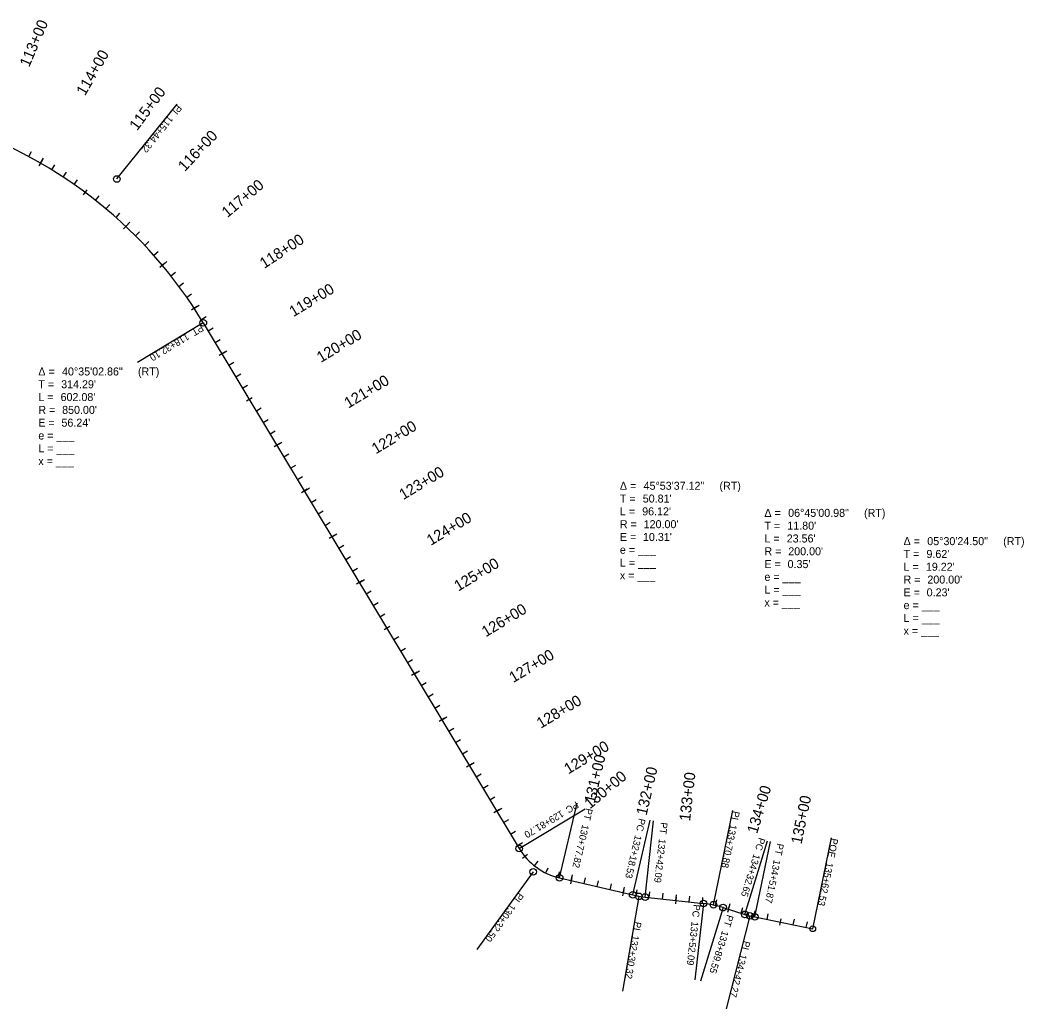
# Model space of a CAD drawing. Extents: x 14106984 to 14110066, y 8637277 to 8639226.
# Drawn here: x 14108185 to 14110066, y 8637277 to 8639130 of the extents above; entities that cross this region are included whole.
import ezdxf

# ---------------------------------------------------------------- set-up
doc = ezdxf.new("R2010")
doc.units = 0
for name, color, linetype in [('Alignment', 7, 'Continuous'), ('Default', 7, 'Continuous'), ('TextAlignment', 7, 'Continuous'), ('TextAlignmentLrg', 7, 'Continuous'), ('TextAlignmentSml', 7, 'Continuous')]:
    doc.layers.add(name, color=color, linetype=linetype)

msp = doc.modelspace()

# ---------------------------------------------------------------- linework, layer by layer
at = {"layer": 'Alignment'}
for p, q in [((14108528.3, 8638562.6), (14109120.4, 8637577.2)), ((14109196.1, 8637522.2), (14109333.1, 8637490.3)), ((14109356.4, 8637486.3), (14109465.7, 8637474.1)), ((14109502.3, 8637466.5), (14109543.5, 8637453.8)), ((14109562.1, 8637449.1), (14109670.5, 8637426.9))]:
    msp.add_line(p, q, dxfattribs=at)
for centre, radius, start, end in [((14107799.7, 8638124.7), 850, 31.0039, 71.588), ((14109223.3, 8637639), 120, 211.0039, 256.8975), ((14109378.5, 8637685), 200, 256.8975, 263.6478), ((14109443.6, 8637275.3), 200, 72.9168, 83.6478), ((14109602.3, 8637645), 200, 252.9168, 258.4236)]:
    msp.add_arc(centre, radius, start, end, dxfattribs=at)
at = {"layer": 'Default'}
for p, q in [((14108528.3, 8638562.6), (14109120.4, 8637577.2)), ((14109196.1, 8637522.2), (14109333.1, 8637490.3)), ((14109356.4, 8637486.3), (14109465.7, 8637474.1)), ((14109502.3, 8637466.5), (14109543.5, 8637453.8)), ((14109562.1, 8637449.1), (14109670.5, 8637426.9))]:
    msp.add_line(p, q, dxfattribs=at)
for centre, radius, start, end in [((14107799.7, 8638124.7), 850, 31.0039, 71.588), ((14109223.3, 8637639), 120, 211.0039, 256.8975), ((14109378.5, 8637685), 200, 256.8975, 263.6478), ((14109443.6, 8637275.3), 200, 72.9168, 83.6478), ((14109602.3, 8637645), 200, 252.9168, 258.4236)]:
    msp.add_arc(centre, radius, start, end, dxfattribs=at)
at = {"layer": 'TextAlignment'}
for p, q in [((14108366.4, 8638832), (14108479, 8638972.4)), ((14108528.3, 8638562.6), (14108404.9, 8638488.4)), ((14109196.1, 8637522.2), (14109228.7, 8637662.4)), ((14109120.4, 8637577.2), (14109243.9, 8637651.4)), ((14109484.4, 8637472), (14109520.9, 8637648.3)), ((14109333.1, 8637490.3), (14109365.8, 8637630.5)), ((14109356.4, 8637486.3), (14109372.3, 8637629.4)), ((14109670.5, 8637426.9), (14109705.4, 8637597.3)), ((14109543.5, 8637453.8), (14109585.8, 8637591.5)), ((14109562.1, 8637449.1), (14109591, 8637590.2)), ((14109146.6, 8637533.7), (14109040.7, 8637388.1)), ((14109344.6, 8637487.6), (14109314.2, 8637310.2)), ((14109465.7, 8637474.1), (14109449.7, 8637331)), ((14109502.3, 8637466.5), (14109460, 8637328.9)), ((14109552.7, 8637451), (14109508.1, 8637276.6))]:
    msp.add_line(p, q, dxfattribs=at)
for centre, radius in [((14108366.4, 8638832), 6.24), ((14108333.4, 8638786.3), 0.05), ((14108528.3, 8638562.6), 6.24), ((14109120.4, 8637577.2), 6.24), ((14109142.3, 8637550.5), 0.05), ((14109146.6, 8637533.7), 6.24), ((14109196.1, 8637522.2), 6.24), ((14109333.1, 8637490.3), 6.24), ((14109344.6, 8637487.6), 6.24), ((14109343, 8637488.2), 0.05), ((14109356.4, 8637486.3), 6.24), ((14109465.7, 8637474.1), 6.24), ((14109484.4, 8637472), 6.24), ((14109502.3, 8637466.5), 6.24), ((14109543.5, 8637453.8), 6.24), ((14109552.7, 8637451), 6.24), ((14109562.1, 8637449.1), 6.24), ((14109556.7, 8637450.3), 0.05), ((14109670.5, 8637426.9), 5.34)]:
    msp.add_circle(centre, radius, dxfattribs=at)
at = {"layer": 'TextAlignmentLrg'}
for p, q in [((14108223, 8638861.8), (14108228.5, 8638871.3)), ((14108310.3, 8638812), (14108303, 8638802.1)), ((14108383.2, 8638742.8), (14108390.7, 8638750.8)), ((14108451.7, 8638670.1), (14108460.1, 8638677.1)), ((14108511.2, 8638589.8), (14108520.4, 8638595.7)), ((14108563.3, 8638504.4), (14108572.6, 8638510)), ((14108620, 8638421.8), (14108609.5, 8638415.5)), ((14108666.3, 8638332.9), (14108675.6, 8638338.6)), ((14108717.8, 8638247.2), (14108727.2, 8638252.9)), ((14108769.3, 8638161.5), (14108778.7, 8638167.1)), ((14108820.8, 8638075.8), (14108830.2, 8638081.4)), ((14108877.6, 8637993.2), (14108867.1, 8637986.9)), ((14108923.8, 8637904.4), (14108933.2, 8637910)), ((14108975.3, 8637818.7), (14108984.7, 8637824.3)), ((14109026.8, 8637733), (14109036.2, 8637738.6)), ((14109078.4, 8637647.2), (14109087.7, 8637652.9)), ((14109135.7, 8637566.2), (14109126.3, 8637558.4)), ((14109217.7, 8637517.1), (14109220.2, 8637527.8)), ((14109315.1, 8637494.5), (14109317.6, 8637505.1)), ((14109413.9, 8637479.9), (14109415.1, 8637490.7)), ((14109512.3, 8637463.4), (14109515.5, 8637473.9)), ((14109610.5, 8637445.4), (14109608, 8637433.4))]:
    msp.add_line(p, q, dxfattribs=at)
for centre in [(14109139, 8637546.7), (14109344.7, 8637487.9), (14109552.8, 8637451.2)]:
    msp.add_circle(centre, 0.05, dxfattribs=at)
at = {"layer": 'TextAlignmentSml'}
for p, q in [((14108201.2, 8638874), (14108206.3, 8638883.6)), ((14108226.1, 8638867.1), (14108220, 8638856.5)), ((14108244.5, 8638849.1), (14108250.3, 8638858.4)), ((14108265.7, 8638835.7), (14108271.6, 8638844.8)), ((14108286.4, 8638821.7), (14108292.6, 8638830.6)), ((14108310.3, 8638812), (14108303, 8638802.1)), ((14108326.5, 8638791.8), (14108333.3, 8638800.4)), ((14108345.9, 8638776.1), (14108352.9, 8638784.4)), ((14108364.8, 8638759.7), (14108372.1, 8638767.9)), ((14108387.4, 8638747.3), (14108379, 8638738.4)), ((14108401.1, 8638725.4), (14108408.9, 8638733.1)), ((14108418.5, 8638707.5), (14108426.5, 8638714.9)), ((14108435.4, 8638689), (14108443.6, 8638696.3)), ((14108456.4, 8638674), (14108447, 8638666.1)), ((14108467.5, 8638650.7), (14108476.1, 8638657.4)), ((14108482.7, 8638630.8), (14108491.4, 8638637.3)), ((14108497.3, 8638610.5), (14108506.2, 8638616.7)), ((14108516.4, 8638593.1), (14108506.1, 8638586.4)), ((14108524.6, 8638568.6), (14108533.9, 8638574.3)), ((14108537.5, 8638547.2), (14108546.9, 8638552.9)), ((14108550.4, 8638525.8), (14108559.7, 8638531.4)), ((14108568.5, 8638507.5), (14108558, 8638501.2)), ((14108576.1, 8638482.9), (14108585.5, 8638488.6)), ((14108589, 8638461.5), (14108598.4, 8638467.1)), ((14108601.9, 8638440.1), (14108611.3, 8638445.7)), ((14108620, 8638421.8), (14108609.5, 8638415.5)), ((14108627.7, 8638397.2), (14108637, 8638402.9)), ((14108640.5, 8638375.8), (14108649.9, 8638381.4)), ((14108653.4, 8638354.4), (14108662.8, 8638360)), ((14108671.5, 8638336.1), (14108661, 8638329.8)), ((14108679.2, 8638311.5), (14108688.5, 8638317.1)), ((14108692, 8638290.1), (14108701.4, 8638295.7)), ((14108704.9, 8638268.7), (14108714.3, 8638274.3)), ((14108723, 8638250.4), (14108712.5, 8638244.1)), ((14108730.7, 8638225.8), (14108740, 8638231.4)), ((14108743.5, 8638204.4), (14108752.9, 8638210)), ((14108756.4, 8638182.9), (14108765.8, 8638188.6)), ((14108774.5, 8638164.7), (14108764.1, 8638158.4)), ((14108782.2, 8638140.1), (14108791.5, 8638145.7)), ((14108795.1, 8638118.7), (14108804.4, 8638124.3)), ((14108807.9, 8638097.2), (14108817.3, 8638102.9)), ((14108826.1, 8638079), (14108815.6, 8638072.7)), ((14108833.7, 8638054.4), (14108843, 8638060)), ((14108846.6, 8638032.9), (14108855.9, 8638038.6)), ((14108859.4, 8638011.5), (14108868.8, 8638017.1)), ((14108877.6, 8637993.2), (14108867.1, 8637986.9)), ((14108885.2, 8637968.7), (14108894.6, 8637974.3)), ((14108898.1, 8637947.2), (14108907.4, 8637952.9)), ((14108911, 8637925.8), (14108920.3, 8637931.4)), ((14108929.1, 8637907.5), (14108918.6, 8637901.2)), ((14108936.7, 8637883), (14108946.1, 8637888.6)), ((14108949.6, 8637861.5), (14108958.9, 8637867.1)), ((14108962.5, 8637840.1), (14108971.8, 8637845.7)), ((14108980.6, 8637821.8), (14108970.1, 8637815.5)), ((14108988.2, 8637797.2), (14108997.6, 8637802.9)), ((14109001.1, 8637775.8), (14109010.5, 8637781.4)), ((14109014, 8637754.4), (14109023.3, 8637760)), ((14109032.1, 8637736.1), (14109021.6, 8637729.8)), ((14109039.7, 8637711.5), (14109049.1, 8637717.1)), ((14109052.6, 8637690.1), (14109062, 8637695.7)), ((14109065.5, 8637668.7), (14109074.8, 8637674.3)), ((14109083.6, 8637650.4), (14109073.1, 8637644.1)), ((14109091.2, 8637625.8), (14109100.6, 8637631.4)), ((14109104.1, 8637604.4), (14109113.5, 8637610)), ((14109117, 8637583), (14109126.4, 8637588.6)), ((14109135.7, 8637566.2), (14109126.3, 8637558.4)), ((14109148.9, 8637544.9), (14109155.7, 8637553.4)), ((14109170, 8637531.5), (14109174.8, 8637541.3)), ((14109193.4, 8637522.8), (14109196.1, 8637533.4)), ((14109219.1, 8637523.1), (14109216.3, 8637511.2)), ((14109242, 8637511.5), (14109244.5, 8637522.1)), ((14109266.4, 8637505.8), (14109268.9, 8637516.4)), ((14109290.7, 8637500.1), (14109293.2, 8637510.8)), ((14109316.5, 8637500.4), (14109313.7, 8637488.5)), ((14109339.5, 8637488.9), (14109341.6, 8637499.6)), ((14109364.2, 8637485.4), (14109365.4, 8637496.3)), ((14109389.1, 8637482.6), (14109390.3, 8637493.5)), ((14109414.6, 8637485.9), (14109413.2, 8637473.8)), ((14109438.8, 8637477.1), (14109440, 8637488)), ((14109463.6, 8637474.3), (14109464.8, 8637485.2)), ((14109488.3, 8637470.3), (14109490.7, 8637480.9)), ((14109514.1, 8637469.3), (14109510.5, 8637457.6)), ((14109536.2, 8637456.1), (14109539.4, 8637466.5)), ((14109560.3, 8637449.5), (14109562.6, 8637460.2)), ((14109584.8, 8637444.4), (14109587, 8637455.1)), ((14109610.5, 8637445.4), (14109608, 8637433.4)), ((14109633.8, 8637434.4), (14109636, 8637445.1)), ((14109658.3, 8637429.4), (14109660.4, 8637440.1))]:
    msp.add_line(p, q, dxfattribs=at)

# ---------------------------------------------------------------- texts
at = {"layer": 'TextAlignment'}
for s, rotation, p in [('PI ', 231.2959, (14108479.2, 8638972.3)), ('115+44.32', 231.2959, (14108463, 8638952.1)), ('PT', 211.0039, (14108523.9, 8638559.7)), ('118+32.10', 211.0039, (14108497.1, 8638543.5)), ('PC', 211.0039, (14109226.7, 8637666.1)), ('129+81.70', 211.0039, (14109199, 8637649.5)), ('PT', 256.8975, (14109245.8, 8637653.5)), ('PI ', 258.2823, (14109521.2, 8637648.2)), ('130+77.82', 256.8975, (14109238.7, 8637623)), ('PC', 256.8975, (14109344.8, 8637634.5)), ('PT', 263.6478, (14109385.7, 8637626.8)), ('133+70.88', 258.2823, (14109515.9, 8637622.9)), ('132+18.53', 256.8975, (14109337.5, 8637603.1)), ('PC', 252.9168, (14109569.4, 8637598.7)), ('132+42.09', 263.6478, (14109382.3, 8637595.7)), ('PT', 258.4236, (14109603.9, 8637587.7)), ('POE ', 258.4236, (14109705.7, 8637597.3)), ('134+32.65', 252.9168, (14109559.9, 8637567.9)), ('134+51.87', 258.4236, (14109597.6, 8637557)), ('135+62.53', 258.4236, (14109696.4, 8637551.8)), ('PI ', 233.9507, (14109119.3, 8637495.7)), ('130+32.50', 233.9507, (14109104.1, 8637474.8)), ('PC', 263.6478, (14109447.1, 8637473)), ('PT', 252.9168, (14109510, 8637454.1)), ('PI ', 260.2726, (14109336.9, 8637440.8)), ('133+52.09', 263.6478, (14109443.5, 8637441)), ('132+30.32', 260.2726, (14109332.5, 8637415.3)), ('133+89.55', 252.9168, (14109500.8, 8637424.2)), ('PI ', 255.6702, (14109541.2, 8637405.1)), ('134+42.27', 255.6702, (14109534.8, 8637380.1))]:
    msp.add_text(s, height=12.96, rotation=rotation, dxfattribs=at).set_placement(p)
for s, p in [('Δ = ', (14108219.1, 8638463.8)), ('40°35\'02.86"', (14108263.5, 8638463.8)), (' (RT)', (14108400.2, 8638463.8)), ('T = ', (14108219.1, 8638439.8)), ("314.29'", (14108261.9, 8638439.8)), ('L = ', (14108219.1, 8638415.8)), ("602.08'", (14108260.8, 8638415.8)), ('R = ', (14108219.1, 8638391.8)), ("850.00'", (14108263.7, 8638391.8)), ('E = ', (14108219.1, 8638367.8)), ("56.24'", (14108262.4, 8638367.8)), ('e = ___ ', (14108219.1, 8638343.8)), ('L = ___', (14108219.1, 8638319.8)), ('x = ___', (14108219.1, 8638295.8))]:
    msp.add_text(s, height=15, dxfattribs=at).set_placement(p)
at = {"layer": 'TextAlignmentLrg'}
for s, rotation, p in [('115+00', 53.3899, (14108404.3, 8638921.4)), ('120+00', 31.0039, (14108748.6, 8638487.2)), ('125+00', 31.0039, (14109006.1, 8638058.6)), ('130+00', 39.7435, (14109252.9, 8637650.4)), ('135+00', 78.4236, (14109649.4, 8637584.3))]:
    msp.add_text(s, height=20.4, rotation=rotation, dxfattribs=at).set_placement(p)
for s, p in [('Δ = ', (14109309, 8638249.6)), ('45°53\'37.12"', (14109353.4, 8638249.6)), (' (RT)', (14109490.1, 8638249.6)), ('T = ', (14109309, 8638225.6)), ("50.81'", (14109351.9, 8638225.6)), ('L = ', (14109309, 8638201.6)), ("96.12'", (14109350.8, 8638201.6)), ('Δ = ', (14109579.9, 8638198.8)), ('06°45\'00.98"', (14109624.4, 8638198.8)), (' (RT)', (14109761.1, 8638198.8)), ('R = ', (14109309, 8638177.6)), ("120.00'", (14109353.6, 8638177.6)), ('T = ', (14109579.9, 8638174.8)), ("11.80'", (14109622.8, 8638174.8)), ('E = ', (14109309, 8638153.6)), ("10.31'", (14109352.3, 8638153.6)), ('L = ', (14109579.9, 8638150.8)), ("23.56'", (14109621.7, 8638150.8)), (' (RT)', (14110021.8, 8638145.8)), ('Δ = ', (14109840.7, 8638145.8)), ('05°30\'24.50"', (14109885.1, 8638145.8)), ('e = ___ ', (14109309, 8638129.6)), ('R = ', (14109579.9, 8638126.8)), ("200.00'", (14109624.6, 8638126.8)), ('T = ', (14109840.7, 8638121.8)), ("9.62'", (14109883.6, 8638121.8)), ('L = ___', (14109309, 8638105.6)), ('E = ', (14109579.9, 8638102.8)), ("0.35'", (14109623.3, 8638102.8)), ('L = ', (14109840.7, 8638097.8)), ("19.22'", (14109882.5, 8638097.8)), ('x = ___', (14109309, 8638081.6)), ('e = ___ ', (14109579.9, 8638078.8)), ('R = ', (14109840.7, 8638073.8)), ("200.00'", (14109885.3, 8638073.8)), ('L = ___', (14109579.9, 8638054.8)), ('E = ', (14109840.7, 8638049.8)), ("0.23'", (14109884, 8638049.8)), ('x = ___', (14109579.9, 8638030.8)), ('e = ___ ', (14109840.7, 8638025.8)), ('L = ___', (14109840.7, 8638001.8)), ('x = ___', (14109840.7, 8637977.8))]:
    msp.add_text(s, height=15, dxfattribs=at).set_placement(p)
at = {"layer": 'TextAlignmentSml'}
for s, rotation, p in [('113+00', 66.8712, (14108201.9, 8639040.4)), ('114+00', 60.1305, (14108306.6, 8638986.8)), ('115+00', 53.3899, (14108404.3, 8638921.4)), ('116+00', 46.6492, (14108493.6, 8638844.9)), ('117+00', 39.9085, (14108573.3, 8638758.5)), ('118+00', 33.1678, (14108642.4, 8638663.3)), ('119+00', 31.0039, (14108697.1, 8638572.9)), ('120+00', 31.0039, (14108748.6, 8638487.2)), ('121+00', 31.0039, (14108800.1, 8638401.5)), ('122+00', 31.0039, (14108851.6, 8638315.8)), ('123+00', 31.0039, (14108903.1, 8638230)), ('124+00', 31.0039, (14108954.6, 8638144.3)), ('125+00', 31.0039, (14109006.1, 8638058.6)), ('126+00', 31.0039, (14109057.7, 8637972.9)), ('127+00', 31.0039, (14109109.2, 8637887.2)), ('128+00', 31.0039, (14109160.7, 8637801.5)), ('129+00', 31.0039, (14109212.2, 8637715.8)), ('131+00', 76.8975, (14109261.6, 8637660.9)), ('132+00', 76.8975, (14109359, 8637638.2)), ('130+00', 39.7435, (14109252.9, 8637650.4)), ('133+00', 83.6478, (14109440.6, 8637627.8)), ('134+00', 72.9168, (14109566.1, 8637603.8)), ('135+00', 78.4236, (14109649.4, 8637584.3))]:
    msp.add_text(s, height=20.4, rotation=rotation, dxfattribs=at).set_placement(p)

doc.saveas('drawing.dxf')
